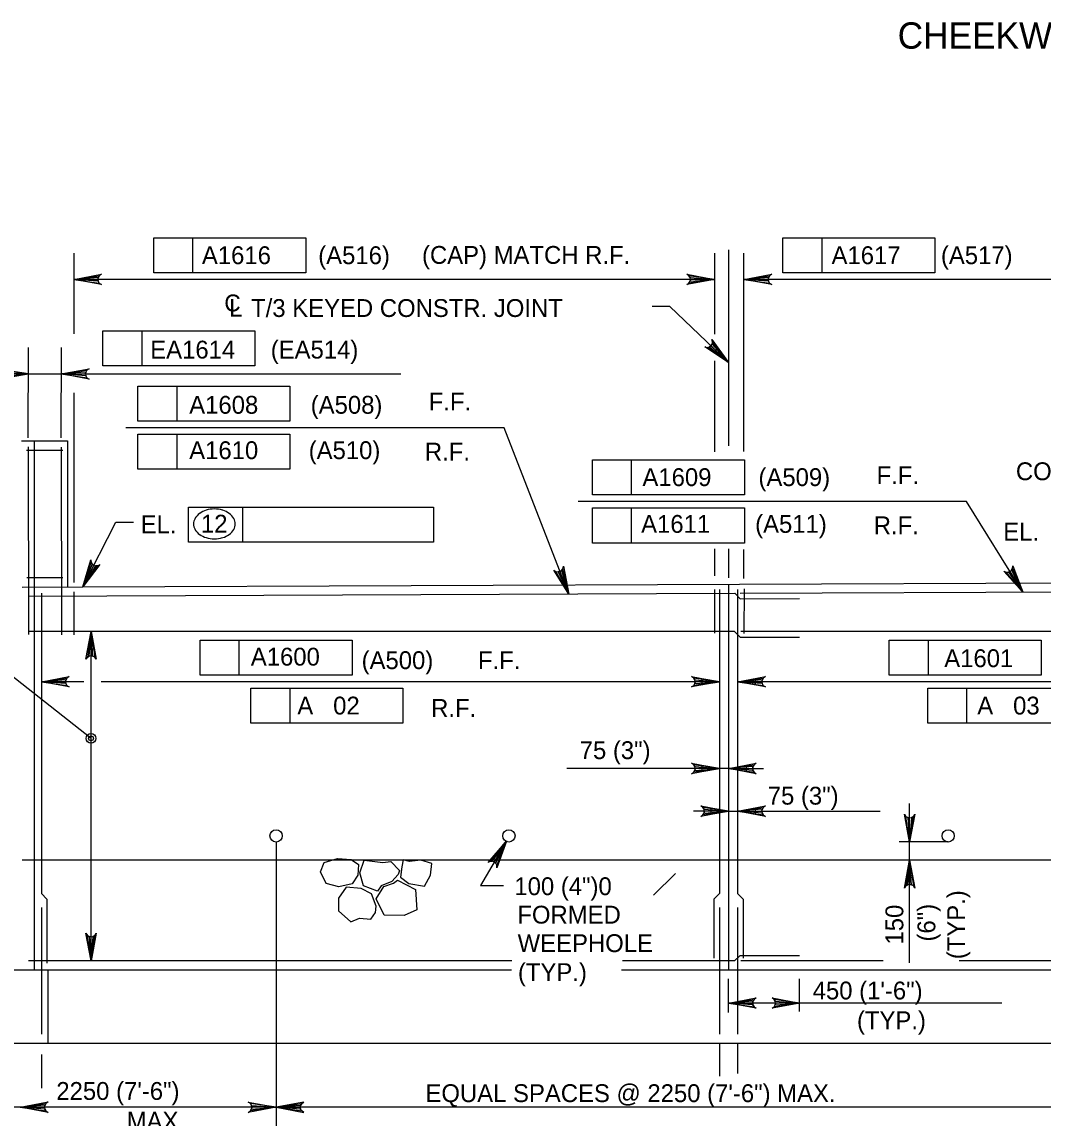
# Model space of a CAD drawing. Extents: x 638340 to 640241, y 295465 to 298435.
# Drawn here: x 638652.2 to 638823.8, y 297348.7 to 297533 of the extents above; entities that cross this region are included whole.
import ezdxf

# ---------------------------------------------------------------- set-up
doc = ezdxf.new("R2010")
doc.units = 0
for name, color, linetype in [('10', 7, 'Continuous'), ('3', 7, 'Continuous'), ('4', 7, 'Continuous'), ('5', 7, 'Continuous')]:
    doc.layers.add(name, color=color, linetype=linetype)

# ---------------------------------------------------------------- blocks, each defined once
blk = doc.blocks.new('ROCK')
at = {"layer": '4'}
for points in [[(2.36725, 1.088), (2.2065, 0.82625), (2.378625, 0.506625), (2.66975, 0.3095), (3.128875, 0.403375), (3.48475, 0.6775), (3.4915, 1.123375), (3.25625, 1.36725), (2.783625, 1.308375)], [(1.10175, -0.02725), (1.4015, -0.159125), (1.78825, -0.148875), (1.980875, -0.266), (2.343375, 0.09475), (2.27875, 0.5505), (1.969375, 0.883), (1.4225, 0.553625), (1.152875, 0.479), (1.0105, 0.082)], [(0.74675, 0.359875), (0.882, 0.16), (1.072875, -0.144), (0.892, -0.457375), (0.448125, -0.758625), (0.1, -0.49325), (-0.095, -0.146375), (0.202875, 0.1025), (0.579125, 0.219875)], [(2.231375, -0.71725), (2.2025, -0.266375), (2.45475, 0.037125), (2.9085, 0.28875), (3.2995, 0.047625), (3.46875, -0.344), (3.231625, -0.855), (2.92, -0.860375), (2.5765, -1.054625), (2.340375, -0.904375)], [(1.2085, -0.192875), (0.778375, -0.737625), (1.008375, -1.391375), (1.48725, -1.396875), (2.09825, -1.106625), (2.133375, -0.486375), (1.723125, -0.203375), (1.37425, -0.239875)]]:
    blk.add_lwpolyline(points, close=True, dxfattribs=at)

msp = doc.modelspace()

# ---------------------------------------------------------------- linework, layer by layer
at = {"layer": '10'}
for p, q in [((638770.94, 297494.69), (638770.94, 297461.73)), ((638652.14, 297462.55), (638659.83, 297462.55)), ((638654.25, 297462.55), (638654.28, 297373.59)), ((638659.83, 297462.55), (638659.86, 297438)), ((638770.94, 297444.39), (638770.94, 297439.51)), ((638662.42, 297438), (638879.47, 297438.93)), ((638770.94, 297438.32), (638770.94, 297373.59)), ((638652.26, 297437.96), (638662.42, 297438)), ((638655.45, 297392.05), (638652.26, 297392.05)), ((638883.15, 297392.05), (638653.79, 297392.05)), ((638734.45, 297373.59), (638573.23, 297373.59)), ((638656.53, 297373.59), (638656.53, 297361.29)), ((638806.35, 297373.59), (638752.98, 297373.59)), ((638954.47, 297373.59), (638806.35, 297373.59)), ((638573.23, 297361.29), (638954.47, 297361.29))]:
    msp.add_line(p, q, dxfattribs=at)
at = {"layer": '3'}
for p, q in [((638674.35, 297496.69), (638699.89, 297496.69)), ((638674.35, 297490.79), (638674.35, 297496.69)), ((638680.94, 297490.79), (638680.94, 297496.69)), ((638699.89, 297496.69), (638699.89, 297490.79)), ((638780.07, 297496.69), (638805.61, 297496.69)), ((638780.07, 297490.79), (638780.07, 297496.69)), ((638786.66, 297490.79), (638786.66, 297496.69)), ((638805.61, 297496.69), (638805.61, 297490.79)), ((638660.9, 297494.14), (638660.9, 297480.56)), ((638768.59, 297494.14), (638768.59, 297480.51)), ((638773.53, 297460.77), (638773.53, 297494.14)), ((638699.89, 297490.79), (638674.35, 297490.79)), ((638805.61, 297490.79), (638780.07, 297490.79)), ((638768.59, 297489.7), (638660.9, 297489.7)), ((638875.9, 297489.7), (638773.53, 297489.7)), ((638761.07, 297485.15), (638758.12, 297485.15)), ((638770.94, 297475.76), (638761.07, 297485.15)), ((638665.8, 297481.05), (638691.34, 297481.05)), ((638665.8, 297475.15), (638665.8, 297481.05)), ((638672.39, 297475.15), (638672.39, 297481.05)), ((638691.34, 297481.05), (638691.34, 297475.15)), ((638653.25, 297463.06), (638653.28, 297478.24)), ((638658.8, 297463.07), (638658.83, 297478.24)), ((638691.34, 297475.15), (638665.8, 297475.15)), ((638768.59, 297476), (638768.59, 297460.71)), ((638653.27, 297473.81), (638647.38, 297473.81)), ((638653.28, 297473.81), (638661.39, 297473.81)), ((638661.38, 297473.81), (638715.88, 297473.81)), ((638664.35, 297473.81), (638667.3, 297473.81)), ((638671.67, 297471.77), (638697.21, 297471.77)), ((638671.67, 297465.86), (638671.67, 297471.77)), ((638678.27, 297465.86), (638678.27, 297471.77)), ((638697.21, 297471.77), (638697.21, 297465.86)), ((638660.9, 297470.63), (638660.9, 297438.77)), ((638697.21, 297465.86), (638671.67, 297465.86)), ((638733.23, 297464.77), (638669.66, 297464.77)), ((638744.08, 297436.81), (638733.23, 297464.77)), ((638671.67, 297463.69), (638697.21, 297463.69)), ((638671.67, 297457.78), (638671.67, 297463.69)), ((638678.27, 297457.78), (638678.27, 297463.69)), ((638697.21, 297463.69), (638697.21, 297457.78)), ((638748.06, 297459.38), (638773.6, 297459.38)), ((638748.06, 297453.47), (638748.06, 297459.38)), ((638754.66, 297453.47), (638754.66, 297459.38)), ((638773.6, 297459.38), (638773.6, 297453.47)), ((638697.21, 297457.78), (638671.67, 297457.78)), ((638773.6, 297453.47), (638748.06, 297453.47)), ((638680.17, 297451.44), (638689.34, 297451.44)), ((638680.17, 297445.54), (638680.17, 297451.44)), ((638689.34, 297445.54), (638689.34, 297451.44)), ((638689.34, 297451.44), (638721.38, 297451.44)), ((638721.38, 297451.44), (638721.38, 297445.54)), ((638810.94, 297452.38), (638745.65, 297452.38)), ((638748.06, 297445.39), (638748.06, 297451.3)), ((638748.06, 297451.3), (638773.6, 297451.3)), ((638754.66, 297445.39), (638754.66, 297451.3)), ((638773.6, 297451.3), (638773.6, 297445.39)), ((638820.4, 297437.14), (638810.94, 297452.38)), ((638662.42, 297438), (638667.98, 297448.92)), ((638667.98, 297448.92), (638670.93, 297448.92)), ((638721.38, 297445.54), (638680.17, 297445.54)), ((638773.6, 297445.39), (638748.06, 297445.39)), ((638768.59, 297444.39), (638768.59, 297439.88)), ((638773.53, 297439.4), (638773.53, 297444.28)), ((638663.81, 297375.13), (638663.81, 297430.5)), ((638682.13, 297429.07), (638707.67, 297429.07)), ((638682.13, 297423.16), (638682.13, 297429.07)), ((638688.73, 297423.16), (638688.73, 297429.07)), ((638707.67, 297429.07), (638707.67, 297423.16)), ((638797.93, 297429.07), (638823.47, 297429.07)), ((638797.93, 297423.16), (638797.93, 297429.07)), ((638804.53, 297423.16), (638804.53, 297429.07)), ((638823.47, 297429.07), (638823.47, 297423.16)), ((638663.81, 297412.55), (638649.26, 297424.03)), ((638769.4, 297425.14), (638769.4, 297422.01)), ((638662.62, 297422.07), (638655.47, 297422.07)), ((638769.4, 297422.07), (638665.5, 297422.07)), ((638707.67, 297423.16), (638682.13, 297423.16)), ((638872.22, 297422.07), (638772.47, 297422.07)), ((638823.47, 297423.16), (638797.93, 297423.16)), ((638690.67, 297415.08), (638690.67, 297420.98)), ((638690.67, 297420.98), (638716.21, 297420.98)), ((638697.26, 297415.08), (638697.26, 297420.98)), ((638716.21, 297420.98), (638716.21, 297415.08)), ((638804.42, 297415.08), (638804.42, 297420.98)), ((638804.42, 297420.98), (638829.96, 297420.98)), ((638811.01, 297415.08), (638811.01, 297420.98)), ((638716.21, 297415.08), (638690.67, 297415.08)), ((638829.96, 297415.08), (638804.42, 297415.08)), ((638763.49, 297407.48), (638743.75, 297407.48)), ((638769.4, 297407.48), (638762.94, 297407.48)), ((638770.94, 297407.48), (638769.4, 297407.48)), ((638770.94, 297407.48), (638776.84, 297407.48)), ((638801.37, 297374.8), (638801.37, 297401.6)), ((638770.94, 297400.32), (638765.03, 297400.32)), ((638770.94, 297400.32), (638772.47, 297400.32)), ((638772.47, 297400.32), (638778.38, 297400.32)), ((638778.38, 297400.32), (638796.41, 297400.32)), ((638733.62, 297395.28), (638729.27, 297387.79)), ((638807.85, 297395.13), (638799.59, 297395.13)), ((638758.31, 297386.16), (638762, 297389.85)), ((638729.27, 297387.79), (638733.14, 297387.79)), ((638770.94, 297366.48), (638770.94, 297372.13)), ((638782.85, 297366.63), (638782.85, 297372.13)), ((638816.87, 297368.05), (638770.94, 297368.05)), ((638769.4, 297361.29), (638769.4, 297355.75)), ((638772.47, 297361.29), (638772.47, 297356.19)), ((638655.47, 297359.38), (638655.47, 297353.74)), ((638884.58, 297350.53), (638603.67, 297350.53))]:
    msp.add_line(p, q, dxfattribs=at)
for points in [[(638660.9, 297489.7), (638665.56, 297490.57), (638665.2, 297490.32), (638665.02, 297490.01), (638664.96, 297489.7), (638665.02, 297489.38), (638665.2, 297489.07), (638665.56, 297488.82), (638660.9, 297489.7), (638665.2, 297489.07), (638665.02, 297489.38), (638660.9, 297489.7), (638664.96, 297489.7), (638665.02, 297490.01), (638660.9, 297489.7), (638665.2, 297490.32)], [(638768.59, 297489.7), (638763.93, 297488.82), (638764.28, 297489.07), (638764.47, 297489.38), (638764.52, 297489.7), (638764.47, 297490.01), (638764.28, 297490.32), (638763.93, 297490.57), (638768.59, 297489.7), (638764.28, 297490.32), (638764.47, 297490.01), (638768.59, 297489.7), (638764.52, 297489.7), (638764.47, 297489.38), (638768.59, 297489.7), (638764.28, 297489.07)], [(638773.53, 297489.7), (638778.19, 297490.57), (638777.83, 297490.32), (638777.65, 297490.01), (638777.6, 297489.7), (638777.65, 297489.38), (638777.83, 297489.07), (638778.19, 297488.82), (638773.53, 297489.7), (638777.83, 297489.07), (638777.65, 297489.38), (638773.53, 297489.7), (638777.6, 297489.7), (638777.65, 297490.01), (638773.53, 297489.7), (638777.83, 297490.32)], [(638770.94, 297475.76), (638766.96, 297478.34), (638767.39, 297478.27), (638767.74, 297478.37), (638767.99, 297478.56), (638768.17, 297478.82), (638768.25, 297479.18), (638768.16, 297479.6), (638770.94, 297475.76), (638768.25, 297479.18), (638768.17, 297478.82), (638770.94, 297475.76), (638767.99, 297478.56), (638767.74, 297478.37), (638770.94, 297475.76), (638767.39, 297478.27)], [(638653.27, 297473.81), (638648.61, 297472.93), (638648.97, 297473.18), (638649.16, 297473.49), (638649.21, 297473.81), (638649.16, 297474.12), (638648.97, 297474.43), (638648.61, 297474.68), (638653.27, 297473.81), (638648.97, 297474.43), (638649.16, 297474.12), (638653.27, 297473.81), (638649.21, 297473.81), (638649.16, 297473.49), (638653.27, 297473.81), (638648.97, 297473.18)], [(638658.81, 297473.81), (638663.47, 297474.68), (638663.11, 297474.43), (638662.93, 297474.12), (638662.88, 297473.81), (638662.93, 297473.49), (638663.11, 297473.18), (638663.47, 297472.93), (638658.81, 297473.81), (638663.11, 297473.18), (638662.93, 297473.49), (638658.81, 297473.81), (638662.88, 297473.81), (638662.93, 297474.12), (638658.81, 297473.81), (638663.11, 297474.43)], [(638662.42, 297438), (638663.76, 297442.55), (638663.81, 297442.12), (638664.01, 297441.81), (638664.26, 297441.62), (638664.57, 297441.53), (638664.93, 297441.55), (638665.31, 297441.76), (638662.42, 297438), (638664.93, 297441.55), (638664.57, 297441.53), (638662.42, 297438), (638664.26, 297441.62), (638664.01, 297441.81), (638662.42, 297438), (638663.81, 297442.12)], [(638744.08, 297436.81), (638741.58, 297440.84), (638741.94, 297440.6), (638742.3, 297440.54), (638742.61, 297440.6), (638742.88, 297440.76), (638743.11, 297441.05), (638743.21, 297441.47), (638744.08, 297436.81), (638743.11, 297441.05), (638742.88, 297440.76), (638744.08, 297436.81), (638742.61, 297440.6), (638742.3, 297440.54), (638744.08, 297436.81), (638741.94, 297440.6)], [(638820.4, 297437.14), (638817.2, 297440.64), (638817.6, 297440.46), (638817.97, 297440.47), (638818.26, 297440.59), (638818.5, 297440.8), (638818.66, 297441.12), (638818.69, 297441.56), (638820.4, 297437.14), (638818.66, 297441.12), (638818.5, 297440.8), (638820.4, 297437.14), (638818.26, 297440.59), (638817.97, 297440.47), (638820.4, 297437.14), (638817.6, 297440.46)], [(638663.81, 297430.5), (638664.68, 297425.84), (638664.44, 297426.2), (638664.12, 297426.38), (638663.81, 297426.44), (638663.5, 297426.38), (638663.19, 297426.2), (638662.94, 297425.84), (638663.81, 297430.5), (638663.19, 297426.2), (638663.5, 297426.38), (638663.81, 297430.5), (638663.81, 297426.44), (638664.12, 297426.38), (638663.81, 297430.5), (638664.44, 297426.2)], [(638655.47, 297422.07), (638660.13, 297422.94), (638659.77, 297422.69), (638659.59, 297422.38), (638659.53, 297422.07), (638659.59, 297421.75), (638659.77, 297421.44), (638660.13, 297421.19), (638655.47, 297422.07), (638659.77, 297421.44), (638659.59, 297421.75), (638655.47, 297422.07), (638659.53, 297422.07), (638659.59, 297422.38), (638655.47, 297422.07), (638659.77, 297422.69)], [(638769.4, 297422.07), (638764.74, 297421.19), (638765.1, 297421.44), (638765.28, 297421.75), (638765.34, 297422.07), (638765.28, 297422.38), (638765.1, 297422.69), (638764.74, 297422.94), (638769.4, 297422.07), (638765.1, 297422.69), (638765.28, 297422.38), (638769.4, 297422.07), (638765.34, 297422.07), (638765.28, 297421.75), (638769.4, 297422.07), (638765.1, 297421.44)], [(638772.47, 297422.07), (638777.13, 297422.94), (638776.78, 297422.69), (638776.59, 297422.38), (638776.54, 297422.07), (638776.59, 297421.75), (638776.78, 297421.44), (638777.13, 297421.19), (638772.47, 297422.07), (638776.78, 297421.44), (638776.59, 297421.75), (638772.47, 297422.07), (638776.54, 297422.07), (638776.59, 297422.38), (638772.47, 297422.07), (638776.78, 297422.69)], [(638769.4, 297407.48), (638764.74, 297406.61), (638765.1, 297406.86), (638765.28, 297407.17), (638765.34, 297407.48), (638765.28, 297407.8), (638765.1, 297408.11), (638764.74, 297408.36), (638769.4, 297407.48), (638765.1, 297408.11), (638765.28, 297407.8), (638769.4, 297407.48), (638765.34, 297407.48), (638765.28, 297407.17), (638769.4, 297407.48), (638765.1, 297406.86)], [(638770.94, 297407.48), (638775.6, 297408.36), (638775.24, 297408.11), (638775.05, 297407.8), (638775, 297407.48), (638775.05, 297407.17), (638775.24, 297406.86), (638775.6, 297406.61), (638770.94, 297407.48), (638775.24, 297406.86), (638775.05, 297407.17), (638770.94, 297407.48), (638775, 297407.48), (638775.05, 297407.8), (638770.94, 297407.48), (638775.24, 297408.11)], [(638770.94, 297400.32), (638766.28, 297399.44), (638766.63, 297399.69), (638766.82, 297400), (638766.87, 297400.32), (638766.82, 297400.63), (638766.63, 297400.94), (638766.28, 297401.19), (638770.94, 297400.32), (638766.63, 297400.94), (638766.82, 297400.63), (638770.94, 297400.32), (638766.87, 297400.32), (638766.82, 297400), (638770.94, 297400.32), (638766.63, 297399.69)], [(638772.47, 297400.32), (638777.13, 297401.19), (638776.78, 297400.94), (638776.59, 297400.63), (638776.54, 297400.32), (638776.59, 297400), (638776.78, 297399.69), (638777.13, 297399.44), (638772.47, 297400.32), (638776.78, 297399.69), (638776.59, 297400), (638772.47, 297400.32), (638776.54, 297400.32), (638776.59, 297400.63), (638772.47, 297400.32), (638776.78, 297400.94)], [(638801.37, 297395.13), (638800.5, 297399.79), (638800.75, 297399.44), (638801.06, 297399.25), (638801.37, 297399.2), (638801.69, 297399.25), (638802, 297399.44), (638802.25, 297399.79), (638801.37, 297395.13), (638802, 297399.44), (638801.69, 297399.25), (638801.37, 297395.13), (638801.37, 297399.2), (638801.06, 297399.25), (638801.37, 297395.13), (638800.75, 297399.44)], [(638733.62, 297395.28), (638732.03, 297390.81), (638732, 297391.25), (638731.82, 297391.57), (638731.58, 297391.77), (638731.28, 297391.88), (638730.92, 297391.88), (638730.52, 297391.69), (638733.62, 297395.28), (638730.92, 297391.88), (638731.28, 297391.88), (638733.62, 297395.28), (638731.58, 297391.77), (638731.82, 297391.57), (638733.62, 297395.28), (638732, 297391.25)], [(638801.37, 297392.05), (638802.25, 297387.39), (638802, 297387.75), (638801.69, 297387.93), (638801.37, 297387.99), (638801.06, 297387.93), (638800.75, 297387.75), (638800.5, 297387.39), (638801.37, 297392.05), (638800.75, 297387.75), (638801.06, 297387.93), (638801.37, 297392.05), (638801.37, 297387.99), (638801.69, 297387.93), (638801.37, 297392.05), (638802, 297387.75)], [(638663.81, 297375.13), (638662.94, 297379.79), (638663.19, 297379.43), (638663.5, 297379.25), (638663.81, 297379.19), (638664.12, 297379.25), (638664.44, 297379.43), (638664.68, 297379.79), (638663.81, 297375.13), (638664.44, 297379.43), (638664.12, 297379.25), (638663.81, 297375.13), (638663.81, 297379.19), (638663.5, 297379.25), (638663.81, 297375.13), (638663.19, 297379.43)], [(638770.94, 297368.05), (638775.6, 297368.92), (638775.24, 297368.67), (638775.05, 297368.36), (638775, 297368.05), (638775.05, 297367.74), (638775.24, 297367.42), (638775.6, 297367.18), (638770.94, 297368.05), (638775.24, 297367.42), (638775.05, 297367.74), (638770.94, 297368.05), (638775, 297368.05), (638775.05, 297368.36), (638770.94, 297368.05), (638775.24, 297368.67)], [(638782.91, 297368.05), (638778.25, 297367.18), (638778.61, 297367.42), (638778.8, 297367.74), (638778.85, 297368.05), (638778.8, 297368.36), (638778.61, 297368.67), (638778.25, 297368.92), (638782.91, 297368.05), (638778.61, 297368.67), (638778.8, 297368.36), (638782.91, 297368.05), (638778.85, 297368.05), (638778.8, 297367.74), (638782.91, 297368.05), (638778.61, 297367.42)]]:
    msp.add_lwpolyline(points, dxfattribs=at)
for points in [[(638768.45, 297477.42), (638769.12, 297478.14), (638770.94, 297475.76)], [(638650.33, 297474.3), (638650.33, 297473.32), (638653.28, 297473.81)], [(638663.32, 297440.86), (638664.2, 297440.41), (638662.42, 297438)], [(638742.55, 297439.4), (638743.47, 297439.75), (638744.06, 297436.81)], [(638818.41, 297439.41), (638819.25, 297439.93), (638820.39, 297437.16)], [(638664.3, 297427.55), (638663.32, 297427.55), (638663.81, 297430.5)], [(638766.45, 297422.56), (638766.45, 297421.58), (638769.4, 297422.07)], [(638775.43, 297422.56), (638775.43, 297421.58), (638772.47, 297422.07)], [(638766.45, 297407.98), (638766.45, 297406.99), (638769.4, 297407.48)], [(638773.89, 297407.98), (638773.89, 297406.99), (638770.94, 297407.48)], [(638767.98, 297400.81), (638767.98, 297399.82), (638770.94, 297400.32)], [(638775.43, 297400.81), (638775.43, 297399.82), (638772.47, 297400.32)], [(638732.57, 297392.5), (638731.72, 297392.99), (638733.63, 297395.3)], [(638801.87, 297389.1), (638800.88, 297389.1), (638801.37, 297392.05)], [(638664.3, 297378.09), (638663.32, 297378.09), (638663.81, 297375.13)]]:
    msp.add_lwpolyline(points, close=True, dxfattribs=at)
for centre, radius in [((638663.81, 297412.55), 0.833), ((638663.81, 297412.55), 0.417), ((638694.9, 297396.15), 1.03), ((638734.03, 297396.15), 1.03), ((638807.85, 297396.15), 1.03)]:
    msp.add_circle(centre, radius, dxfattribs=at)
for centre, radius, start, end in [((638684.54, 297446.24), 4.87, 90, 106.5358), ((638684.54, 297446.24), 4.87, 73.4642, 90), ((638682.87, 297448.6), 1.83, 149.9767, 180), ((638683.67, 297448.13), 2.76, 125.6316, 149.9767), ((638684.2, 297447.4), 3.66, 106.5358, 125.6316), ((638684.89, 297447.4), 3.66, 54.3684, 73.4642), ((638685.42, 297448.13), 2.76, 30.0233, 54.3684), ((638686.22, 297448.6), 1.83, 0, 30.0233), ((638682.87, 297448.6), 1.83, 180, 210.0233), ((638683.67, 297449.06), 2.76, 210.0233, 234.3684), ((638685.42, 297449.06), 2.76, 305.6316, 329.9767), ((638686.22, 297448.6), 1.83, 329.9767, 0), ((638684.2, 297449.8), 3.66, 234.3684, 253.4642), ((638684.54, 297450.96), 4.87, 253.4642, 270), ((638684.54, 297450.96), 4.87, 270, 286.5358), ((638684.89, 297449.8), 3.66, 286.5358, 305.6316)]:
    msp.add_arc(centre, radius, start, end, dxfattribs=at)
at = {"layer": '4'}
for points in [[(638651.92, 297350.54), (638656.58, 297351.42), (638656.22, 297351.17), (638656.04, 297350.86), (638655.98, 297350.54), (638656.04, 297350.23), (638656.22, 297349.92), (638656.58, 297349.67), (638651.92, 297350.54), (638656.22, 297349.92), (638656.04, 297350.23), (638651.92, 297350.54), (638655.98, 297350.54), (638656.04, 297350.86), (638651.92, 297350.54), (638656.22, 297351.17)], [(638694.9, 297350.53), (638690.24, 297349.66), (638690.6, 297349.91), (638690.79, 297350.22), (638690.84, 297350.53), (638690.79, 297350.85), (638690.6, 297351.16), (638690.24, 297351.41), (638694.9, 297350.53), (638690.6, 297351.16), (638690.79, 297350.85), (638694.9, 297350.53), (638690.84, 297350.53), (638690.79, 297350.22), (638694.9, 297350.53), (638690.6, 297349.91)], [(638694.9, 297350.53), (638699.56, 297349.66), (638699.21, 297349.91), (638699.02, 297350.22), (638698.97, 297350.53), (638699.02, 297350.85), (638699.21, 297351.16), (638699.56, 297351.41), (638694.9, 297350.53), (638699.21, 297351.16), (638699.02, 297350.85), (638694.9, 297350.53), (638698.97, 297350.53), (638699.02, 297350.22), (638694.9, 297350.53), (638699.21, 297349.91)]]:
    msp.add_lwpolyline(points, dxfattribs=at)
at = {"layer": '5'}
for p, q in [((638652.99, 297461.01), (638659.06, 297461.01)), ((638653.25, 297461.53), (638653.28, 297429.99)), ((638658.79, 297461.52), (638658.83, 297429.98)), ((638659.06, 297439.54), (638653.02, 297439.54)), ((638653.28, 297436.43), (638771.97, 297436.93)), ((638655.47, 297436.94), (638655.47, 297386.47)), ((638660.91, 297437.17), (638660.9, 297429.98)), ((638768.59, 297437.55), (638768.58, 297430.21)), ((638769.4, 297437.55), (638769.4, 297386.47)), ((638771.97, 297436.93), (638772.91, 297436)), ((638772.47, 297437.56), (638772.47, 297386.47)), ((638772.91, 297436.94), (638883.66, 297437.41)), ((638773.54, 297437.69), (638773.53, 297430.2)), ((638772.91, 297436), (638782.85, 297436.04)), ((638771.96, 297430.5), (638653.28, 297430.5)), ((638771.96, 297430.5), (638772.89, 297429.56)), ((638772.89, 297429.56), (638782.84, 297429.56)), ((638883.66, 297430.5), (638773.01, 297430.5)), ((638694.9, 297395.13), (638694.9, 297347.15)), ((638655.47, 297386.47), (638656.4, 297385.53)), ((638656.4, 297385.53), (638656.4, 297374.77)), ((638769.4, 297386.47), (638768.46, 297385.53)), ((638768.46, 297385.53), (638768.46, 297375.59)), ((638772.47, 297386.47), (638773.41, 297385.53)), ((638773.41, 297385.53), (638773.41, 297375.59)), ((638655.47, 297384.14), (638655.47, 297362.83)), ((638769.4, 297384.14), (638769.4, 297362.83)), ((638772.47, 297384.14), (638772.47, 297362.83)), ((638771.96, 297375.13), (638772.89, 297376.07)), ((638772.89, 297376.07), (638782.84, 297376.07)), ((638734.52, 297375.13), (638653.28, 297375.13)), ((638771.96, 297375.13), (638753.13, 297375.13)), ((638796.94, 297375.13), (638773.01, 297375.13)), ((638883.66, 297375.13), (638809.71, 297375.13))]:
    msp.add_line(p, q, dxfattribs=at)

# ---------------------------------------------------------------- block references
at = {"layer": '3', "xscale": 4.921475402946, "yscale": -4.921475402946, "rotation": -156.2166383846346}
msp.add_blockref('ROCK', (638720.35, 297391.99), dxfattribs=at)

# ---------------------------------------------------------------- texts
at = {"layer": '3'}
for s, height, p in [('CHEEKWALL B DETAIL', 4.4294, (638799.36, 297528.49)), ('A1616', 3, (638682.44, 297492.27)), ('(A516)', 3, (638701.99, 297492.27)), ('(CAP) MATCH R.F.', 3.0001, (638719.43, 297492.32)), ('A1617', 3, (638788.25, 297492.27)), ('(A517)', 3, (638806.63, 297492.27)), ('C', 2.84, (638686.21, 297484.32)), ('L', 3, (638687.01, 297483.43)), ('T/3 KEYED CONSTR. JOINT', 3.0001, (638690.71, 297483.39)), ('EA1614', 3, (638673.76, 297476.4)), ('(EA514)', 3, (638694.01, 297476.4)), ('A1608', 3, (638680.31, 297467.12)), ('(A508)', 3, (638700.73, 297467.12)), ('F.F.', 3, (638720.55, 297467.68)), ('A1610', 3, (638680.31, 297459.49)), ('(A510)', 3, (638700.39, 297459.49)), ('R.F.', 3, (638719.91, 297459.25)), ('CONSTR. JT. (TYP.)', 3.0001, (638819.23, 297455.95)), ('A1609', 3, (638756.47, 297454.96)), ('(A509)', 3, (638775.97, 297454.96)), ('F.F.', 3, (638795.82, 297455.29)), ('EL.', 3, (638672.15, 297447.02)), ('12', 3, (638682.28, 297447.14)), ('A1611', 3, (638756.25, 297447.1)), ('(A511)', 3, (638775.41, 297447.1)), ('R.F.', 3, (638795.34, 297446.86)), ('EL.', 3, (638817.1, 297445.79)), ('A1600', 3, (638690.66, 297424.78)), ('(A500)', 3, (638709.28, 297424.19)), ('F.F.', 3, (638728.83, 297424.19)), ('A1601', 3, (638807.19, 297424.52)), ('A   02', 3, (638698.48, 297416.56)), ('R.F.', 3, (638720.96, 297416.16)), ('A   03', 3, (638812.74, 297416.56)), ('75 (3")', 3, (638745.93, 297409.06)), ('75 (3")', 3, (638777.53, 297401.41)), ('100 (4")0', 3, (638734.95, 297386.19)), ('FORMED', 3, (638735.45, 297381.41)), ('WEEPHOLE', 3, (638735.5, 297376.62)), ('(TYP.)', 3, (638735.55, 297371.75)), ('450 (1\'-6")', 3.0001, (638785.08, 297368.66)), ('(TYP.)', 3, (638792.52, 297363.66)), ('2250 (7\'-6")', 3.0001, (638657.98, 297351.77)), ('EQUAL SPACES @ 2250 (7\'-6") MAX.', 3.0001, (638720.01, 297351.4)), ('MAX.', 3, (638669.81, 297346.77))]:
    msp.add_text(s, height=height, dxfattribs=at).set_placement(p)
for s, p in [('(TYP.)', (638810.69, 297375.42)), ('150', (638800.31, 297377.89)), ('(6")', (638805.69, 297378.4))]:
    msp.add_text(s, height=3, rotation=90, dxfattribs=at).set_placement(p)

doc.saveas('drawing.dxf')
